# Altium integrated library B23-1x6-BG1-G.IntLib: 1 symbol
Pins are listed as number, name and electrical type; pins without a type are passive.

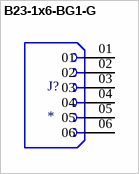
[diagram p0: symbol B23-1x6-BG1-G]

## B23-1x6-BG1-G
designator J?
MP: B23-1x6-BG1-G
footprint VALCON_B23-1x6-BG1-G
pins: 01, 02, 03, 04, 05, 06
